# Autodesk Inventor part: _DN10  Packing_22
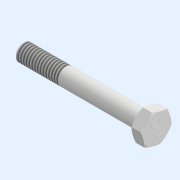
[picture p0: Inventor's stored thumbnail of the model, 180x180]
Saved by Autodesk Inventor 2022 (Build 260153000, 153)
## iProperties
Created: 2021-12
Part Number: _DN10  Packing_22
Material: Generico
Document SubType Name: Modeling
Designer: admin
Density: 1 g/cm^3
Appearance: Default
Author: admin
Revision Number: NONE
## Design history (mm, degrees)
feature "_DN10  Packing"
feature "Filettatura1" dims "d0" = 15, "d1" = 0
node "Solido1"
